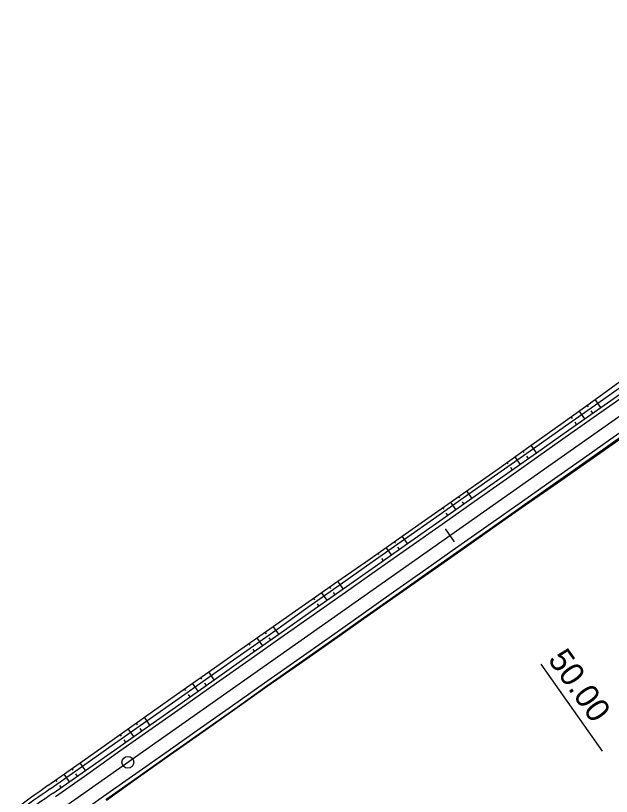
# Model space of a CAD drawing. Extents: x -481645 to -478728, y -1113199 to -1110710.
# Drawn here: x -480468.2 to -480392.6, y -1112820.8 to -1112721.8 of the extents above; entities that cross this region are included whole.
import ezdxf

# ---------------------------------------------------------------- set-up
doc = ezdxf.new("R2010")
doc.units = 0
for name, color, linetype in [('Vrstva 52', 7, 'Continuous'), ('Vrstva 53', 7, 'Continuous'), ('Vrstva 54', 7, 'Continuous'), ('Vrstva 55', 7, 'Continuous'), ('Vrstva 56', 7, 'Continuous'), ('Vrstva 57', 7, 'Continuous'), ('Vrstva 58', 7, 'Continuous'), ('Vrstva 60', 7, 'Continuous'), ('Vrstva 61', 7, 'Continuous'), ('Vrstva 62', 7, 'Continuous')]:
    doc.layers.add(name, color=color, linetype=linetype)

msp = doc.modelspace()

# ---------------------------------------------------------------- linework, layer by layer
at = {"layer": 'Vrstva 52'}
msp.add_line((-480462.955, -1112822.861), (-480319.487, -1112721.759), dxfattribs=at)
at = {"layer": 'Vrstva 53'}
for p, q in [((-480394.662, -1112770.461), (-480390.609, -1112767.532)), ((-480398.719, -1112773.384), (-480394.662, -1112770.461)), ((-480402.788, -1112776.289), (-480398.719, -1112773.384)), ((-480395.342, -1112778.176), (-480391.241, -1112775.315)), ((-480406.855, -1112779.199), (-480402.788, -1112776.289)), ((-480399.442, -1112781.037), (-480395.342, -1112778.176)), ((-480410.949, -1112782.068), (-480406.855, -1112779.199)), ((-480403.541, -1112783.9), (-480399.442, -1112781.037)), ((-480415.044, -1112784.938), (-480410.949, -1112782.068)), ((-480407.634, -1112786.773), (-480403.541, -1112783.9)), ((-480419.137, -1112787.809), (-480415.044, -1112784.938)), ((-480411.727, -1112789.645), (-480407.634, -1112786.773)), ((-480423.23, -1112790.681), (-480419.137, -1112787.809)), ((-480415.819, -1112792.517), (-480411.727, -1112789.645)), ((-480427.323, -1112793.553), (-480423.23, -1112790.681)), ((-480419.912, -1112795.39), (-480415.819, -1112792.517)), ((-480431.416, -1112796.425), (-480427.323, -1112793.553)), ((-480424.005, -1112798.262), (-480419.912, -1112795.39)), ((-480435.51, -1112799.296), (-480431.416, -1112796.425)), ((-480428.097, -1112801.134), (-480424.005, -1112798.262)), ((-480439.603, -1112802.167), (-480435.51, -1112799.296)), ((-480432.189, -1112804.008), (-480428.097, -1112801.134)), ((-480443.697, -1112805.037), (-480439.603, -1112802.167)), ((-480436.282, -1112806.88), (-480432.189, -1112804.008)), ((-480447.781, -1112807.921), (-480443.697, -1112805.037)), ((-480440.367, -1112809.763), (-480436.282, -1112806.88)), ((-480451.866, -1112810.806), (-480447.781, -1112807.921)), ((-480444.453, -1112812.645), (-480440.367, -1112809.763)), ((-480455.94, -1112813.704), (-480451.866, -1112810.806)), ((-480448.538, -1112815.528), (-480444.453, -1112812.645)), ((-480460.019, -1112816.595), (-480455.94, -1112813.704)), ((-480452.609, -1112818.431), (-480448.538, -1112815.528)), ((-480464.098, -1112819.487), (-480460.019, -1112816.595)), ((-480456.678, -1112821.337), (-480452.609, -1112818.431))]:
    msp.add_line(p, q, dxfattribs=at)
msp.add_arc((-480406.481, -1112903.285), 101.694, 124.51148, 127.36704, dxfattribs=at)
at = {"layer": 'Vrstva 54'}
for p, q in [((-480394.329, -1112770.933), (-480390.242, -1112768.053)), ((-480398.416, -1112773.813), (-480394.329, -1112770.933)), ((-480402.504, -1112776.693), (-480398.416, -1112773.813)), ((-480406.591, -1112779.573), (-480402.504, -1112776.693)), ((-480410.678, -1112782.453), (-480406.591, -1112779.573)), ((-480414.765, -1112785.334), (-480410.678, -1112782.453)), ((-480418.852, -1112788.214), (-480414.765, -1112785.334)), ((-480422.939, -1112791.094), (-480418.852, -1112788.214)), ((-480427.026, -1112793.974), (-480422.939, -1112791.094)), ((-480431.113, -1112796.854), (-480427.026, -1112793.974)), ((-480435.201, -1112799.734), (-480431.113, -1112796.854)), ((-480439.288, -1112802.615), (-480435.201, -1112799.734)), ((-480443.375, -1112805.495), (-480439.288, -1112802.615)), ((-480447.462, -1112808.375), (-480443.375, -1112805.495)), ((-480451.549, -1112811.255), (-480447.462, -1112808.375)), ((-480455.636, -1112814.135), (-480451.549, -1112811.255)), ((-480459.723, -1112817.016), (-480455.636, -1112814.135)), ((-480463.81, -1112819.896), (-480459.723, -1112817.016))]:
    msp.add_line(p, q, dxfattribs=at)
msp.add_arc((-480406.78, -1112903.808), 101.458, 124.20143, 127.05815, dxfattribs=at)
at = {"layer": 'Vrstva 55'}
for p, q in [((-480393.945, -1112771.478), (-480389.858, -1112768.597)), ((-480398.032, -1112774.358), (-480393.945, -1112771.478)), ((-480402.12, -1112777.238), (-480398.032, -1112774.358)), ((-480395.44, -1112778.036), (-480391.353, -1112775.156)), ((-480406.207, -1112780.118), (-480402.12, -1112777.238)), ((-480399.527, -1112780.916), (-480395.44, -1112778.036)), ((-480410.294, -1112782.998), (-480406.207, -1112780.118)), ((-480403.615, -1112783.796), (-480399.527, -1112780.916)), ((-480414.381, -1112785.878), (-480410.294, -1112782.998)), ((-480407.702, -1112786.677), (-480403.615, -1112783.796)), ((-480418.468, -1112788.759), (-480414.381, -1112785.878)), ((-480411.789, -1112789.557), (-480407.702, -1112786.677)), ((-480422.555, -1112791.639), (-480418.468, -1112788.759)), ((-480415.876, -1112792.437), (-480411.789, -1112789.557)), ((-480426.642, -1112794.519), (-480422.555, -1112791.639)), ((-480419.963, -1112795.317), (-480415.876, -1112792.437)), ((-480430.729, -1112797.399), (-480426.642, -1112794.519)), ((-480424.05, -1112798.197), (-480419.963, -1112795.317)), ((-480434.817, -1112800.279), (-480430.729, -1112797.399)), ((-480428.137, -1112801.078), (-480424.05, -1112798.197)), ((-480438.904, -1112803.159), (-480434.817, -1112800.279)), ((-480432.224, -1112803.958), (-480428.137, -1112801.078)), ((-480442.991, -1112806.04), (-480438.904, -1112803.159)), ((-480436.312, -1112806.838), (-480432.224, -1112803.958)), ((-480447.078, -1112808.92), (-480442.991, -1112806.04)), ((-480440.399, -1112809.718), (-480436.312, -1112806.838)), ((-480451.165, -1112811.8), (-480447.078, -1112808.92)), ((-480444.486, -1112812.598), (-480440.399, -1112809.718)), ((-480455.252, -1112814.68), (-480451.165, -1112811.8)), ((-480448.573, -1112815.478), (-480444.486, -1112812.598)), ((-480459.339, -1112817.56), (-480455.252, -1112814.68)), ((-480452.66, -1112818.359), (-480448.573, -1112815.478)), ((-480463.426, -1112820.441), (-480459.339, -1112817.56)), ((-480456.747, -1112821.239), (-480452.66, -1112818.359))]:
    msp.add_line(p, q, dxfattribs=at)
msp.add_arc((-480406.585, -1112904.079), 101.125, 124.20019, 127.05879, dxfattribs=at)
at = {"layer": 'Vrstva 56'}
for p, q in [((-480393.657, -1112771.886), (-480389.57, -1112769.006)), ((-480397.744, -1112774.766), (-480393.657, -1112771.886)), ((-480401.832, -1112777.647), (-480397.744, -1112774.766)), ((-480395.728, -1112777.627), (-480391.641, -1112774.747)), ((-480405.919, -1112780.527), (-480401.832, -1112777.647)), ((-480399.815, -1112780.508), (-480395.728, -1112777.627)), ((-480410.006, -1112783.407), (-480405.919, -1112780.527)), ((-480403.903, -1112783.388), (-480399.815, -1112780.508)), ((-480414.093, -1112786.287), (-480410.006, -1112783.407)), ((-480407.99, -1112786.268), (-480403.903, -1112783.388)), ((-480418.18, -1112789.167), (-480414.093, -1112786.287)), ((-480412.077, -1112789.148), (-480407.99, -1112786.268)), ((-480422.267, -1112792.047), (-480418.18, -1112789.167)), ((-480416.164, -1112792.028), (-480412.077, -1112789.148)), ((-480426.354, -1112794.928), (-480422.267, -1112792.047)), ((-480420.251, -1112794.908), (-480416.164, -1112792.028)), ((-480430.441, -1112797.808), (-480426.354, -1112794.928)), ((-480424.338, -1112797.789), (-480420.251, -1112794.908)), ((-480434.529, -1112800.688), (-480430.441, -1112797.808)), ((-480428.425, -1112800.669), (-480424.338, -1112797.789)), ((-480438.616, -1112803.568), (-480434.529, -1112800.688)), ((-480432.512, -1112803.549), (-480428.425, -1112800.669)), ((-480442.703, -1112806.448), (-480438.616, -1112803.568)), ((-480436.6, -1112806.429), (-480432.512, -1112803.549)), ((-480446.79, -1112809.329), (-480442.703, -1112806.448)), ((-480440.687, -1112809.309), (-480436.6, -1112806.429)), ((-480450.877, -1112812.209), (-480446.79, -1112809.329)), ((-480444.774, -1112812.189), (-480440.687, -1112809.309)), ((-480454.964, -1112815.089), (-480450.877, -1112812.209)), ((-480448.861, -1112815.07), (-480444.774, -1112812.189)), ((-480459.051, -1112817.969), (-480454.964, -1112815.089)), ((-480452.948, -1112817.95), (-480448.861, -1112815.07)), ((-480463.138, -1112820.849), (-480459.051, -1112817.969)), ((-480457.035, -1112820.83), (-480452.948, -1112817.95)), ((-480461.122, -1112823.71), (-480457.035, -1112820.83))]:
    msp.add_line(p, q, dxfattribs=at)
at = {"layer": 'Vrstva 57'}
for p, q in [((-480393.657, -1112771.886), (-480389.57, -1112769.006)), ((-480397.744, -1112774.766), (-480393.657, -1112771.886)), ((-480401.832, -1112777.647), (-480397.744, -1112774.766)), ((-480395.728, -1112777.627), (-480391.641, -1112774.747)), ((-480405.919, -1112780.527), (-480401.832, -1112777.647)), ((-480399.815, -1112780.508), (-480395.728, -1112777.627)), ((-480410.006, -1112783.407), (-480405.919, -1112780.527)), ((-480403.903, -1112783.388), (-480399.815, -1112780.508)), ((-480414.093, -1112786.287), (-480410.006, -1112783.407)), ((-480407.99, -1112786.268), (-480403.903, -1112783.388)), ((-480418.18, -1112789.167), (-480414.093, -1112786.287)), ((-480412.077, -1112789.148), (-480407.99, -1112786.268)), ((-480422.267, -1112792.047), (-480418.18, -1112789.167)), ((-480416.164, -1112792.028), (-480412.077, -1112789.148)), ((-480426.354, -1112794.928), (-480422.267, -1112792.047)), ((-480420.251, -1112794.908), (-480416.164, -1112792.028)), ((-480430.441, -1112797.808), (-480426.354, -1112794.928)), ((-480424.338, -1112797.789), (-480420.251, -1112794.908)), ((-480434.529, -1112800.688), (-480430.441, -1112797.808)), ((-480428.425, -1112800.669), (-480424.338, -1112797.789)), ((-480438.616, -1112803.568), (-480434.529, -1112800.688)), ((-480432.512, -1112803.549), (-480428.425, -1112800.669)), ((-480442.703, -1112806.448), (-480438.616, -1112803.568)), ((-480436.6, -1112806.429), (-480432.512, -1112803.549)), ((-480446.79, -1112809.329), (-480442.703, -1112806.448)), ((-480440.687, -1112809.309), (-480436.6, -1112806.429)), ((-480450.877, -1112812.209), (-480446.79, -1112809.329)), ((-480444.774, -1112812.189), (-480440.687, -1112809.309)), ((-480454.964, -1112815.089), (-480450.877, -1112812.209)), ((-480448.861, -1112815.07), (-480444.774, -1112812.189)), ((-480459.051, -1112817.969), (-480454.964, -1112815.089)), ((-480452.948, -1112817.95), (-480448.861, -1112815.07)), ((-480463.138, -1112820.849), (-480459.051, -1112817.969)), ((-480457.035, -1112820.83), (-480452.948, -1112817.95)), ((-480461.122, -1112823.71), (-480457.035, -1112820.83))]:
    msp.add_line(p, q, dxfattribs=at)
at = {"layer": 'Vrstva 58'}
for p, q in [((-480412.509, -1112788.535), (-480413.661, -1112786.9)), ((-480401.564, -1112804.066), (-480393.788, -1112815.101))]:
    msp.add_line(p, q, dxfattribs=at)
at = {"layer": 'Vrstva 60'}
msp.add_circle((-480453.956, -1112816.519), 0.75, dxfattribs=at)
at = {"layer": 'Vrstva 61'}
for p, q in [((-480393.945, -1112771.478), (-480394.662, -1112770.461)), ((-480395.989, -1112772.918), (-480396.69, -1112771.922)), ((-480395.514, -1112771.422), (-480395.676, -1112771.192)), ((-480394.967, -1112772.198), (-480395.159, -1112771.926)), ((-480397.55, -1112772.873), (-480397.705, -1112772.653)), ((-480397.011, -1112773.638), (-480397.203, -1112773.366)), ((-480402.12, -1112777.238), (-480402.788, -1112776.289)), ((-480404.163, -1112778.678), (-480404.821, -1112777.744)), ((-480403.665, -1112777.215), (-480403.805, -1112777.017)), ((-480403.141, -1112777.958), (-480403.333, -1112777.686)), ((-480405.704, -1112778.662), (-480405.838, -1112778.471)), ((-480405.185, -1112779.398), (-480405.377, -1112779.126)), ((-480411.836, -1112782.98), (-480411.973, -1112782.786)), ((-480410.294, -1112782.998), (-480410.949, -1112782.068)), ((-480412.337, -1112784.438), (-480412.996, -1112783.503)), ((-480411.316, -1112783.718), (-480411.508, -1112783.446)), ((-480413.882, -1112784.417), (-480414.02, -1112784.22)), ((-480413.359, -1112785.158), (-480413.551, -1112784.886)), ((-480418.468, -1112788.759), (-480419.137, -1112787.809)), ((-480420.017, -1112788.73), (-480420.16, -1112788.527)), ((-480420.512, -1112790.199), (-480421.184, -1112789.245)), ((-480419.49, -1112789.479), (-480419.682, -1112789.206)), ((-480422.062, -1112790.168), (-480422.207, -1112789.963)), ((-480421.533, -1112790.919), (-480421.725, -1112790.646)), ((-480426.642, -1112794.519), (-480427.323, -1112793.553)), ((-480428.197, -1112794.482), (-480428.346, -1112794.271)), ((-480430.242, -1112795.92), (-480430.393, -1112795.707)), ((-480428.686, -1112795.959), (-480429.37, -1112794.989)), ((-480427.664, -1112795.239), (-480427.856, -1112794.966)), ((-480429.708, -1112796.679), (-480429.9, -1112796.406)), ((-480434.817, -1112800.279), (-480435.51, -1112799.296)), ((-480436.86, -1112801.719), (-480437.556, -1112800.731)), ((-480436.378, -1112800.234), (-480436.533, -1112800.013)), ((-480435.838, -1112800.999), (-480436.03, -1112800.727)), ((-480438.423, -1112801.672), (-480438.58, -1112801.449)), ((-480437.882, -1112802.439), (-480438.074, -1112802.167)), ((-480442.991, -1112806.04), (-480443.697, -1112805.037)), ((-480445.034, -1112807.48), (-480445.739, -1112806.479)), ((-480444.558, -1112805.986), (-480444.718, -1112805.758)), ((-480444.013, -1112806.76), (-480444.205, -1112806.488)), ((-480446.6, -1112807.428), (-480446.76, -1112807.2)), ((-480446.056, -1112808.2), (-480446.248, -1112807.928)), ((-480452.728, -1112811.752), (-480452.884, -1112811.53)), ((-480451.165, -1112811.8), (-480451.866, -1112810.806)), ((-480453.209, -1112813.24), (-480453.903, -1112812.255)), ((-480452.187, -1112812.52), (-480452.379, -1112812.248)), ((-480454.768, -1112813.198), (-480454.921, -1112812.98)), ((-480454.23, -1112813.96), (-480454.422, -1112813.688)), ((-480459.339, -1112817.56), (-480460.019, -1112816.595)), ((-480460.892, -1112817.527), (-480461.039, -1112817.318)), ((-480461.383, -1112819), (-480462.059, -1112818.041)), ((-480460.361, -1112818.28), (-480460.553, -1112818.008)), ((-480462.934, -1112818.97), (-480463.078, -1112818.764)), ((-480462.405, -1112819.72), (-480462.597, -1112819.448))]:
    msp.add_line(p, q, dxfattribs=at)
at = {"layer": 'Vrstva 62'}
for p, q in [((-480393.397, -1112776.596), (-480393.291, -1112776.746)), ((-480394.419, -1112777.316), (-480394.368, -1112777.388)), ((-480394.316, -1112777.461), (-480394.316, -1112777.461)), ((-480399.527, -1112780.916), (-480399.442, -1112781.037)), ((-480400.549, -1112781.636), (-480400.508, -1112781.694)), ((-480400.467, -1112781.753), (-480400.467, -1112781.753)), ((-480401.571, -1112782.356), (-480401.492, -1112782.469)), ((-480402.593, -1112783.076), (-480402.555, -1112783.13)), ((-480402.517, -1112783.185), (-480402.517, -1112783.185)), ((-480407.702, -1112786.677), (-480407.634, -1112786.773)), ((-480408.723, -1112787.397), (-480408.69, -1112787.444)), ((-480408.657, -1112787.491), (-480408.657, -1112787.491)), ((-480410.767, -1112788.837), (-480410.735, -1112788.882)), ((-480409.745, -1112788.117), (-480409.68, -1112788.209)), ((-480410.703, -1112788.927), (-480410.703, -1112788.927)), ((-480415.876, -1112792.437), (-480415.819, -1112792.517)), ((-480416.898, -1112793.157), (-480416.87, -1112793.196)), ((-480416.842, -1112793.235), (-480416.842, -1112793.235)), ((-480418.941, -1112794.597), (-480418.915, -1112794.634)), ((-480418.889, -1112794.672), (-480418.889, -1112794.672)), ((-480417.919, -1112793.877), (-480417.866, -1112793.954)), ((-480424.05, -1112798.197), (-480424.005, -1112798.262)), ((-480426.094, -1112799.637), (-480426.051, -1112799.698)), ((-480425.072, -1112798.917), (-480425.05, -1112798.948)), ((-480425.028, -1112798.98), (-480425.028, -1112798.98)), ((-480427.116, -1112800.357), (-480427.095, -1112800.386)), ((-480427.074, -1112800.416), (-480427.074, -1112800.416)), ((-480433.246, -1112804.678), (-480433.229, -1112804.702)), ((-480432.224, -1112803.958), (-480432.189, -1112804.008)), ((-480434.268, -1112805.398), (-480434.236, -1112805.444)), ((-480433.212, -1112804.726), (-480433.212, -1112804.726)), ((-480435.29, -1112806.118), (-480435.274, -1112806.14)), ((-480435.259, -1112806.162), (-480435.259, -1112806.162)), ((-480441.42, -1112810.438), (-480441.404, -1112810.46)), ((-480441.389, -1112810.483), (-480441.389, -1112810.483)), ((-480440.399, -1112809.718), (-480440.367, -1112809.763)), ((-480442.442, -1112811.158), (-480442.41, -1112811.204)), ((-480443.464, -1112811.878), (-480443.448, -1112811.901)), ((-480443.431, -1112811.924), (-480443.431, -1112811.924)), ((-480448.573, -1112815.478), (-480448.538, -1112815.528)), ((-480449.595, -1112816.198), (-480449.576, -1112816.226)), ((-480449.556, -1112816.253), (-480449.556, -1112816.253)), ((-480450.616, -1112816.918), (-480450.574, -1112816.979)), ((-480451.638, -1112817.639), (-480451.614, -1112817.672)), ((-480451.591, -1112817.705), (-480451.591, -1112817.705))]:
    msp.add_line(p, q, dxfattribs=at)

# ---------------------------------------------------------------- texts
at = {"layer": 'Vrstva 58'}
msp.add_text('50.00', height=2.999, rotation=305.17217, dxfattribs=at).set_placement((-480400.747, -1112803.489))

doc.saveas('drawing.dxf')
